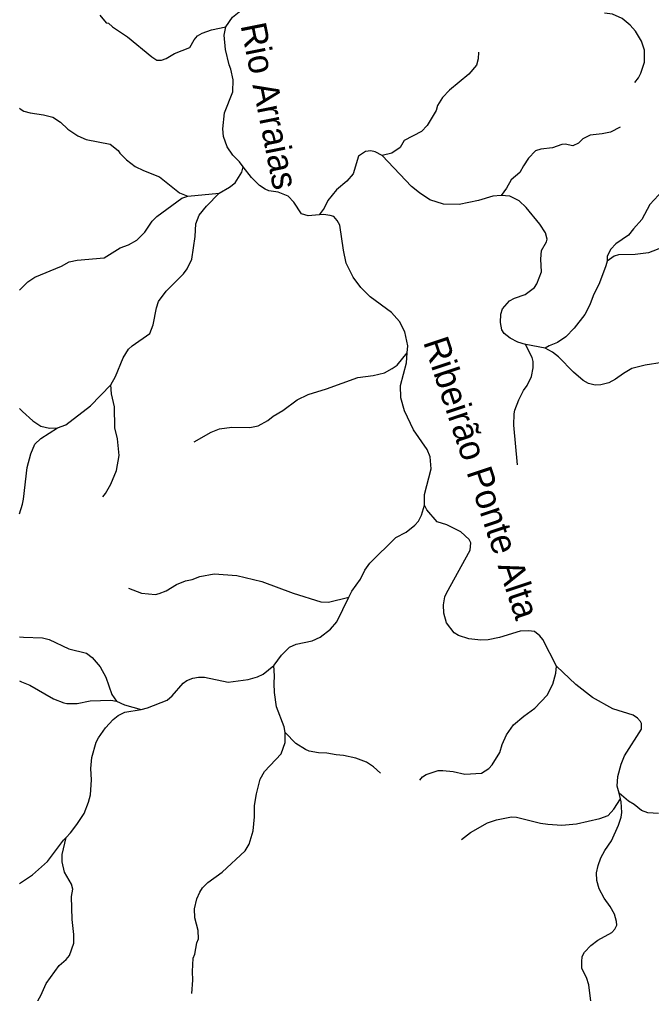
# Model space of a CAD drawing. Extents: x 500 to 555.2, y 9115.7 to 9171.
# Drawn here: x 500 to 504.94, y 9122.45 to 9130.07 of the extents above; entities that cross this region are included whole.
import ezdxf
from ezdxf.enums import TextEntityAlignment as Align

# ---------------------------------------------------------------- set-up
doc = ezdxf.new("R2010")
doc.units = 0
doc.header["$LTSCALE"] = 0.064
doc.layers.add('61', color=7, linetype='Continuous')
doc.layers.add('7', color=7, linetype='Continuous', lineweight=25)

msp = doc.modelspace()

# ---------------------------------------------------------------- linework, layer by layer
at = {"layer": '7'}
for points in [[(501.6139, 9130.0118), (501.6666, 9130.0873), (501.7307, 9130.1387), (501.8191, 9130.1824), (501.9543, 9130.197), (502.0712, 9130.2006), (502.2141, 9130.2315), (502.2797, 9130.2643), (502.3251, 9130.2967), (502.4433, 9130.4114), (502.5696, 9130.577), (502.612, 9130.6947), (502.6309, 9130.7382)], [(500.6284, 9130.103), (500.679, 9130.0431), (500.6951, 9130.0393), (500.7277, 9130.0109), (500.8461, 9129.9329), (501.0358, 9129.7759), (501.0743, 9129.7518), (501.1112, 9129.7509), (501.1479, 9129.7624), (501.2118, 9129.804), (501.3322, 9129.8488), (501.3662, 9129.9099), (501.3913, 9129.9399), (501.4294, 9129.962), (501.5012, 9129.9887), (501.6139, 9130.0118)], [(504.8122, 9129.5756), (504.8407, 9129.6124), (504.8596, 9129.6485), (504.8893, 9129.7345), (504.888, 9129.8294), (504.8665, 9129.8995), (504.8179, 9129.9779), (504.7774, 9130.025), (504.7141, 9130.0756), (504.6391, 9130.1098), (504.5764, 9130.1172)], [(501.7498, 9128.9159), (501.7205, 9128.9561), (501.6696, 9129.007), (501.6243, 9129.0732), (501.5964, 9129.1529), (501.5909, 9129.2145), (501.6038, 9129.3385), (501.6692, 9129.5026), (501.6727, 9129.5957), (501.6537, 9129.6811), (501.6396, 9129.7146), (501.6104, 9129.8352), (501.6007, 9129.9464), (501.6139, 9130.0118)], [(503.5904, 9129.8129), (503.5872, 9129.7602), (503.5737, 9129.7116), (503.5147, 9129.6411), (503.3632, 9129.5171), (503.3086, 9129.4593), (503.2709, 9129.3971), (503.2589, 9129.3576), (503.19, 9129.2391), (503.1442, 9129.1922), (503.01, 9129.1216), (502.9765, 9129.0671), (502.9123, 9129.0225), (502.8363, 9129.0057)], [(499.9999, 9129.3752), (500.0138, 9129.3653), (500.0336, 9129.3512), (500.084, 9129.3379), (500.1883, 9129.3233), (500.2611, 9129.3042), (500.3212, 9129.2653), (500.3784, 9129.2118), (500.4576, 9129.1595), (500.5208, 9129.1295), (500.7089, 9129.0943), (500.7722, 9129.0438), (500.784, 9129.0225), (500.8368, 9128.9713), (500.904, 9128.9201), (500.9694, 9128.8871), (501.0954, 9128.8371), (501.2527, 9128.7138), (501.3169, 9128.6875)], [(504.6976, 9129.2255), (504.6241, 9129.187), (504.5575, 9129.1736), (504.4644, 9129.1635), (504.4064, 9129.1347), (504.3723, 9129.1027), (504.3294, 9129.0819), (504.2672, 9129.093), (504.2427, 9129.0916), (504.1704, 9129.0652), (504.0769, 9129.0552), (504.0359, 9129.0427), (503.9823, 9128.984), (503.9414, 9128.9241), (503.9146, 9128.8729), (503.8459, 9128.8136), (503.8104, 9128.7493), (503.7677, 9128.6915)], [(502.8363, 9129.0057), (502.7828, 9129.034), (502.7481, 9129.0404), (502.7057, 9129.0353), (502.6528, 9128.9999), (502.609, 9128.8629), (502.5606, 9128.8049), (502.4799, 9128.7355), (502.4131, 9128.654), (502.383, 9128.5944), (502.3449, 9128.5415)], [(503.7677, 9128.6915), (503.7028, 9128.686), (503.5905, 9128.6531), (503.4401, 9128.6221), (503.3164, 9128.6257), (503.211, 9128.659), (503.1302, 9128.7125), (503.0671, 9128.7635), (502.8363, 9129.0057)], [(505.5545, 9128.9781), (505.41, 9128.9063), (505.3509, 9128.8664), (505.2891, 9128.8473), (505.2355, 9128.8421), (505.1704, 9128.8193), (505.1011, 9128.7798), (505.0318, 9128.7303), (504.9295, 9128.6216), (504.8678, 9128.5055), (504.8017, 9128.4328), (504.7627, 9128.381), (504.6642, 9128.3148), (504.6254, 9128.2729), (504.5976, 9128.2172), (504.5967, 9128.1781)], [(501.5625, 9128.7104), (501.6433, 9128.7568), (501.6875, 9128.7913), (501.7401, 9128.8739), (501.7498, 9128.9159)], [(502.3449, 9128.5415), (502.2585, 9128.5325), (502.2051, 9128.5479), (502.1452, 9128.6404), (502.1029, 9128.6873), (502.0245, 9128.7173), (501.9511, 9128.7292), (501.9206, 9128.7421), (501.8779, 9128.77), (501.8143, 9128.8319), (501.7498, 9128.9159)], [(499.9999, 9127.9512), (500.0135, 9127.9649), (500.0654, 9128.017), (500.1206, 9128.0545), (500.3279, 9128.1402), (500.3889, 9128.1738), (500.4499, 9128.1877), (500.6618, 9128.2057), (500.7865, 9128.2841), (500.8527, 9128.3075), (500.9167, 9128.3433), (500.9797, 9128.4064), (501.0381, 9128.4927), (501.0741, 9128.5288), (501.271, 9128.6715), (501.3169, 9128.6875), (501.5625, 9128.7104)], [(500.7141, 9127.2114), (500.7523, 9127.2768), (500.8117, 9127.4233), (500.8531, 9127.4894), (500.8812, 9127.5171), (501.0193, 9127.6133), (501.045, 9127.6801), (501.0709, 9127.8137), (501.088, 9127.8623), (501.1484, 9127.9438), (501.2841, 9128.0794), (501.3106, 9128.1193), (501.3492, 9128.1951), (501.3741, 9128.3708), (501.379, 9128.4716), (501.4055, 9128.5387), (501.4641, 9128.6087), (501.5625, 9128.7104)], [(503.7659, 9127.7638), (503.7776, 9127.8055), (503.8337, 9127.868), (503.873, 9127.8893), (503.9555, 9127.9185), (504.028, 9127.9741), (504.0464, 9128.0016), (504.0823, 9128.0965), (504.0775, 9128.1949), (504.083, 9128.2624), (504.1231, 9128.33), (504.1265, 9128.3511), (504.1154, 9128.4002), (504.0713, 9128.4693), (503.9623, 9128.5982), (503.9085, 9128.6501), (503.8365, 9128.6862), (503.7677, 9128.6915)], [(503.0331, 9127.4607), (503.0371, 9127.5169), (503.0146, 9127.626), (502.9731, 9127.7059), (502.9108, 9127.7762), (502.7435, 9127.9011), (502.6697, 9127.9733), (502.61, 9128.0527), (502.5566, 9128.1628), (502.5342, 9128.2658), (502.5061, 9128.4605), (502.4862, 9128.4975), (502.4589, 9128.5268), (502.4312, 9128.5368), (502.3781, 9128.5435), (502.3449, 9128.5415)], [(505.4015, 9128.464), (505.3514, 9128.4187), (505.2819, 9128.3733), (505.1776, 9128.3274), (505.036, 9128.2878), (504.9211, 9128.2436), (504.815, 9128.2303), (504.6851, 9128.2286), (504.6523, 9128.219), (504.5967, 9128.1781)], [(504.5967, 9128.1781), (504.5873, 9128.141), (504.5361, 9128.0091), (504.4886, 9127.9074), (504.4626, 9127.836), (504.4217, 9127.7618), (504.3379, 9127.6538), (504.2747, 9127.5879), (504.2093, 9127.5417), (504.1438, 9127.517), (504.112, 9127.4977)], [(503.9587, 9127.5274), (503.8992, 9127.5443), (503.8369, 9127.5755), (503.7907, 9127.612), (503.7723, 9127.6429), (503.7626, 9127.6995), (503.7659, 9127.7638)], [(503.895, 9126.587), (503.8676, 9126.8952), (503.869, 9126.9859), (503.8741, 9127.0132), (503.9048, 9127.0944), (503.9436, 9127.1668), (503.9717, 9127.2066), (504.0051, 9127.2768), (504.0173, 9127.3438), (504.0184, 9127.394), (504.0101, 9127.4264), (503.9587, 9127.5274)], [(504.112, 9127.4977), (503.9608, 9127.5268), (503.9587, 9127.5274)], [(505.0262, 9127.3874), (504.8937, 9127.3658), (504.7908, 9127.3384), (504.7238, 9127.3003), (504.663, 9127.2563), (504.6095, 9127.2284), (504.5479, 9127.2117), (504.5039, 9127.2085), (504.4509, 9127.2218), (504.4085, 9127.2455), (504.3323, 9127.3097), (504.2175, 9127.4308), (504.1702, 9127.4663), (504.112, 9127.4977)], [(501.3667, 9126.7649), (501.4984, 9126.8406), (501.5634, 9126.8685), (501.6618, 9126.8802), (501.8014, 9126.8788), (501.8669, 9126.8905), (501.9416, 9126.9321), (501.984, 9126.9659), (502.0611, 9127.0112), (502.1732, 9127.0936), (502.2572, 9127.1364), (502.4017, 9127.1791), (502.6457, 9127.2702), (502.7667, 9127.2841), (502.8564, 9127.3064), (502.9151, 9127.3383), (502.953, 9127.3667), (503.0331, 9127.4607)], [(503.1691, 9126.2701), (503.169, 9126.3534), (503.2194, 9126.5557), (503.2112, 9126.6473), (503.1899, 9126.7047), (503.0827, 9126.861), (503.0115, 9127.0094), (502.9834, 9127.109), (502.9802, 9127.2067), (503.0275, 9127.3833), (503.0331, 9127.4607)], [(500.2984, 9126.8746), (500.3614, 9126.8999), (500.5546, 9127.0481), (500.7141, 9127.2114)], [(500.6507, 9126.336), (500.6715, 9126.3611), (500.7138, 9126.4355), (500.7585, 9126.5422), (500.7787, 9126.6584), (500.7674, 9126.7889), (500.7445, 9126.876), (500.7444, 9127.0389), (500.7186, 9127.1425), (500.7141, 9127.2114)], [(499.9999, 9127.0258), (500.0246, 9127.0034), (500.1043, 9126.9312), (500.1677, 9126.8871), (500.2353, 9126.8739), (500.2984, 9126.8746)], [(499.9999, 9126.2023), (500.0231, 9126.2775), (500.0319, 9126.3162), (500.059, 9126.5653), (500.0889, 9126.6722), (500.1202, 9126.7478), (500.1676, 9126.7921), (500.2984, 9126.8746)], [(502.5772, 9125.5516), (502.5994, 9125.597), (502.6668, 9125.6928), (502.7021, 9125.7614), (502.7402, 9125.8169), (502.9449, 9126.0188), (503.025, 9126.0589), (503.0929, 9126.1139), (503.122, 9126.1444), (503.1437, 9126.1922), (503.1691, 9126.2701)], [(504.1998, 9125.0121), (504.0929, 9125.22), (504.0714, 9125.2492), (504.0281, 9125.2825), (503.9817, 9125.2876), (503.9167, 9125.2843), (503.756, 9125.2352), (503.6648, 9125.2184), (503.6085, 9125.2155), (503.5156, 9125.2261), (503.4337, 9125.2522), (503.3991, 9125.2717), (503.3396, 9125.35), (503.3181, 9125.4254), (503.3164, 9125.491), (503.3278, 9125.5527), (503.3397, 9125.5835), (503.5259, 9125.9188), (503.5295, 9125.9765), (503.5178, 9126.0013), (503.453, 9126.063), (503.3426, 9126.1176), (503.2678, 9126.1415), (503.1853, 9126.2331), (503.1691, 9126.2701)], [(500.8515, 9125.6221), (500.9539, 9125.5816), (501.0632, 9125.5732), (501.0915, 9125.5788), (501.1481, 9125.6019), (501.2281, 9125.6514), (501.2989, 9125.678), (501.3519, 9125.6897), (501.4094, 9125.7121), (501.5235, 9125.7336), (501.7007, 9125.7205), (501.8959, 9125.6731), (502.1414, 9125.5815), (502.3571, 9125.5142), (502.4175, 9125.5107), (502.5772, 9125.5516)], [(501.9896, 9125.0174), (501.991, 9125.0185), (502.0489, 9125.0982), (502.1113, 9125.1599), (502.165, 9125.1843), (502.289, 9125.2087), (502.3508, 9125.2373), (502.4326, 9125.3009), (502.4828, 9125.3583), (502.5772, 9125.5516)], [(499.9999, 9125.2404), (500.031, 9125.2389), (500.1787, 9125.2319), (500.232, 9125.2189), (500.3863, 9125.1479), (500.5236, 9125.1123), (500.5689, 9125.0793), (500.6316, 9125.005), (500.6753, 9124.9248), (500.7229, 9124.7896), (500.7593, 9124.7388)], [(500.9526, 9124.6718), (501.0025, 9124.6859), (501.1551, 9124.7467), (501.1951, 9124.7787), (501.2792, 9124.8775), (501.3092, 9124.8992), (501.3547, 9124.9185), (501.4005, 9124.9267), (501.4472, 9124.9251), (501.6316, 9124.8874), (501.7883, 9124.9072), (501.8621, 9124.9276), (501.9073, 9124.9497), (501.9896, 9125.0174)], [(502.0787, 9124.4917), (502.0692, 9124.537), (502.0115, 9124.6947), (501.994, 9124.8046), (501.991, 9124.8749), (501.9959, 9124.9347), (501.9896, 9125.0174)], [(503.1314, 9124.1202), (503.1535, 9124.1471), (503.1805, 9124.1634), (503.2758, 9124.195), (503.3104, 9124.1968), (503.3912, 9124.1886), (503.4832, 9124.1675), (503.6127, 9124.174), (503.6713, 9124.2124), (503.6977, 9124.2389), (503.7564, 9124.3374), (503.7758, 9124.3984), (503.8085, 9124.474), (503.8647, 9124.5528), (503.9442, 9124.6213), (504.0299, 9124.684), (504.1283, 9124.7841), (504.1721, 9124.8698), (504.1952, 9124.9574), (504.1998, 9125.0121)], [(504.6899, 9124.0186), (504.6763, 9124.0719), (504.6812, 9124.1493), (504.7072, 9124.2438), (504.7333, 9124.3094), (504.8663, 9124.5201), (504.8648, 9124.5642), (504.8581, 9124.5791), (504.8347, 9124.6041), (504.8009, 9124.6281), (504.6418, 9124.6791), (504.4817, 9124.7657), (504.3518, 9124.8688), (504.1998, 9125.0121)], [(499.9999, 9124.8967), (500.0158, 9124.89), (500.0799, 9124.863), (500.2649, 9124.7565), (500.3456, 9124.7248), (500.3704, 9124.7201), (500.4499, 9124.7201), (500.5541, 9124.7397), (500.715, 9124.7463), (500.7593, 9124.7388)], [(500.7593, 9124.7388), (500.8224, 9124.7093), (500.9526, 9124.6718)], [(500.3644, 9123.6719), (500.3986, 9123.708), (500.4491, 9123.7721), (500.5057, 9123.8593), (500.5405, 9123.9477), (500.556, 9124.0064), (500.5623, 9124.1216), (500.5592, 9124.2123), (500.5669, 9124.2976), (500.6001, 9124.4183), (500.6174, 9124.4518), (500.673, 9124.5303), (500.7333, 9124.5943), (500.7712, 9124.6252), (500.825, 9124.6506), (500.9526, 9124.6718)], [(501.3481, 9122.4505), (501.3562, 9122.5549), (501.353, 9122.6249), (501.3577, 9122.7276), (501.3709, 9122.7597), (501.3876, 9122.8469), (501.4005, 9122.8803), (501.3971, 9122.9453), (501.3711, 9123.0445), (501.368, 9123.114), (501.3864, 9123.1926), (501.4095, 9123.2452), (501.4307, 9123.2787), (501.4723, 9123.3186), (501.5864, 9123.4001), (501.7658, 9123.5682), (501.7967, 9123.6198), (501.8284, 9123.7247), (501.8385, 9123.8344), (501.8385, 9123.9223), (501.8535, 9124.013), (501.8819, 9124.1271), (501.9157, 9124.1874), (502.0463, 9124.326), (502.0791, 9124.4136), (502.0787, 9124.4917)], [(502.8246, 9124.175), (502.768, 9124.2251), (502.7139, 9124.2618), (502.6317, 9124.2921), (502.5345, 9124.3135), (502.4759, 9124.3174), (502.4039, 9124.3313), (502.3387, 9124.3332), (502.2667, 9124.3478), (502.2368, 9124.3602), (502.1625, 9124.4069), (502.0787, 9124.4917)], [(503.457, 9123.6571), (503.5291, 9123.711), (503.6608, 9123.7867), (503.7318, 9123.8103), (503.8484, 9123.8343), (503.8878, 9123.8309), (504.0755, 9123.7836), (504.1333, 9123.7749), (504.2435, 9123.7688), (504.3582, 9123.7777), (504.5388, 9123.8209), (504.6055, 9123.8428), (504.6502, 9123.8939), (504.7013, 9123.9739)], [(504.4684, 9122.826), (504.5237, 9122.8698), (504.6335, 9122.9289), (504.658, 9122.9536), (504.6712, 9122.9861), (504.671, 9123.0149), (504.6532, 9123.0732), (504.6204, 9123.1323), (504.5737, 9123.1977), (504.5349, 9123.2708), (504.5156, 9123.3351), (504.5139, 9123.3947), (504.5254, 9123.4538), (504.5464, 9123.5122), (504.5786, 9123.5706), (504.6305, 9123.6444), (504.686, 9123.7687), (504.7069, 9123.8296), (504.7107, 9123.8671), (504.707, 9123.9518), (504.7013, 9123.9739), (504.6899, 9124.0186)], [(504.9984, 9123.8601), (504.9145, 9123.8648), (504.8661, 9123.8824), (504.809, 9123.9294), (504.7626, 9123.9545), (504.6899, 9124.0186)], [(499.9999, 9122.1917), (500.0192, 9122.213), (500.058, 9122.2559), (500.1096, 9122.3335), (500.1664, 9122.4355), (500.2074, 9122.5307), (500.3093, 9122.6708), (500.3651, 9122.7185), (500.3901, 9122.7485), (500.4247, 9122.8443), (500.4262, 9122.9125), (500.4112, 9123.0297), (500.4066, 9123.2104), (500.4161, 9123.2668), (500.4063, 9123.3079), (500.3519, 9123.4008), (500.3327, 9123.4807), (500.3343, 9123.5385), (500.3644, 9123.6719)], [(499.9999, 9123.3119), (500.0231, 9123.3275), (500.1025, 9123.3809), (500.2191, 9123.4829), (500.3435, 9123.6498), (500.3644, 9123.6719)], [(504.4682, 9122.3913), (504.4547, 9122.5188), (504.435, 9122.5779), (504.3991, 9122.6476), (504.3979, 9122.6983), (504.4024, 9122.7419), (504.4205, 9122.7737), (504.4684, 9122.826)]]:
    msp.add_lwpolyline(points, dxfattribs=at)

# ---------------------------------------------------------------- texts
at = {"layer": '61'}
for s, rotation, p in [('Rio Arraias', 281.326, (501.858, 9129.3748)), ('Ribeirão Ponte Alta', 288.435, (503.52, 9126.4536))]:
    msp.add_text(s, height=0.2, rotation=rotation, dxfattribs=at).set_placement(p, align=Align.CENTER)

doc.saveas('drawing.dxf')
